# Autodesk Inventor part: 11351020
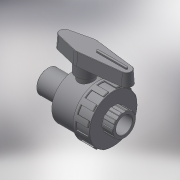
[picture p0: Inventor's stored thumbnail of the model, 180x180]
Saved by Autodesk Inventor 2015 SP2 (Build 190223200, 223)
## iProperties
Created: 2017-11
Part Number: 11351020
Material: Generic
Description: PLASSON 1/NUT VALVE FEMALE THREADED 2" PVC
Document SubType Name: Modeling
Designer: KIM
Density: 1 g/cm^3
Appearance: Default
Author: KIM
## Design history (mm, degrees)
derived "113510.ipt"
feature "Solid1::113510.ipt"
tag "TaggingFeature1"
body "Solid1"
other parameters: "d0" = 166, "d2" = 118, "d4" = 45.3248, "d8" = 106.2, "d13" = 1.69968, "d25" = 1.13312, "d26" = 1.69968, "d29" = 28.5, "d30" = 0, "d35" = 1.69968, "d39" = 59, "d45" = 360 deg, "d47" = 1.13312, "d50" = 64.9, "d51" = 35.4, "d53" = 0, "d55" = 11.3312, "d56" = 5.6656, "d57" = 26.6, "d58" = 0, "d59" = 1.69968, "d63" = 47.2, "d64" = 106, "d66" = 129, "d68" = 23.6, "d69" = 38.7, "d70" = 26.5, "d71" = 3 deg, "d73" = 2.36, "d74" = 51.6, "d75" = 3.18, "d76" = 0, "d77" = 1.13312, "d78" = 56.656, "d79" = 38, "d80" = 118, "d81" = 38, "d82" = 113.28, "d83" = 26.6, "d84" = 79.3184, "d85" = 56.656, "d86" = 79.3184, "d87" = 120 deg, "d88" = 38, "d90" = 360 deg, "d92" = 17.7, "d95" = 8.85, "G_" = 56.656, "l_" = 38, "H_" = 166, "K_" = 118, "F_" = 106, "J_" = 129, "d67" = 47.2, "d72" = 11.8
